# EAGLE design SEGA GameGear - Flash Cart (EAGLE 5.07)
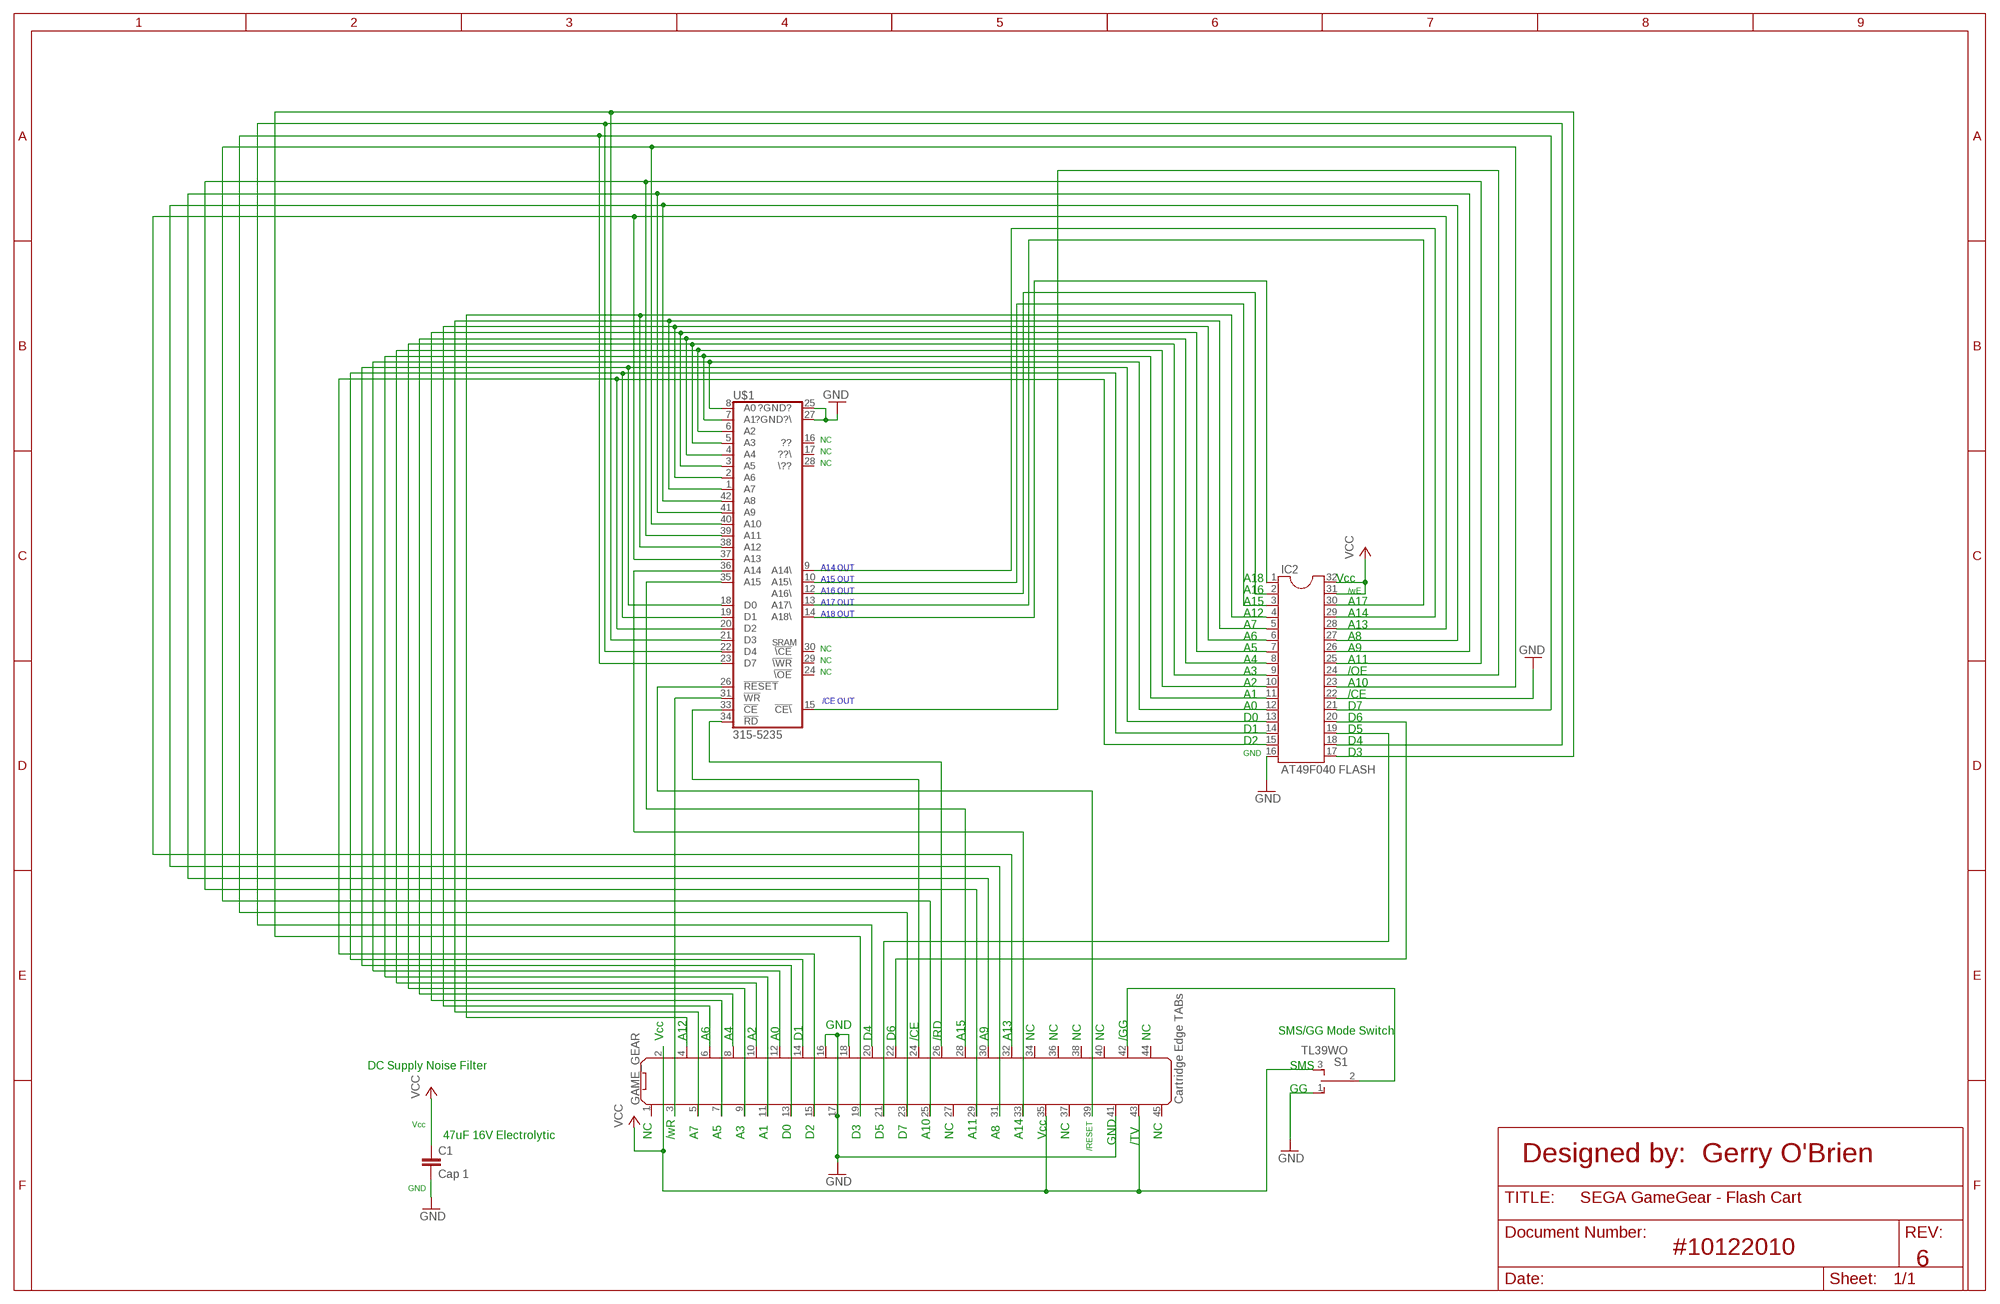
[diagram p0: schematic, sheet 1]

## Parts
C1  Cap 1  C7.5/3  [C7.5B3]
GAME_GEAR  Cartridge Edge TABs  SIP24  [ZIP45]
IC2  AT49F040 FLASH  DIL32  [DIL32]
S1  TL39WO  [TL3XWO]
U$1  315-5235  [DIL42-6.07]

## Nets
GND: C1.2 GAME_GEAR.16 GAME_GEAR.17 GAME_GEAR.18 GAME_GEAR.41 IC2.16 IC2.22 S1.1(O) U$1.25(?GND?) U$1.27(?GND?\)
N$1: GAME_GEAR.4 IC2.4 U$1.38(A12)
N$2: GAME_GEAR.5 IC2.5 U$1.1(A7)
N$3: GAME_GEAR.25 IC2.23 U$1.40(A10)
N$4: GAME_GEAR.29 IC2.25 U$1.39(A11)
N$5: GAME_GEAR.30 IC2.26 U$1.41(A9)
N$6: GAME_GEAR.6 IC2.6 U$1.2(A6)
N$7: GAME_GEAR.32 IC2.28 U$1.37(A13)
N$8: GAME_GEAR.23 IC2.21 U$1.23(D7)
N$9: GAME_GEAR.20 IC2.18 U$1.22(D4)
N$10: GAME_GEAR.12 IC2.12 U$1.8(A0)
N$11: GAME_GEAR.22 IC2.20
N$12: GAME_GEAR.19 IC2.17 U$1.21(D3)
N$13: IC2.24 U$1.15(!CE\)
N$14: GAME_GEAR.14 IC2.14 U$1.19(D1)
N$15: GAME_GEAR.15 IC2.15 U$1.20(D2)
N$16: GAME_GEAR.13 IC2.13 U$1.18(D0)
N$17: GAME_GEAR.8 IC2.8 U$1.4(A4)
N$18: GAME_GEAR.11 IC2.11 U$1.7(A1)
N$19: GAME_GEAR.10 IC2.10 U$1.6(A2)
N$20: GAME_GEAR.21 IC2.19
N$21: GAME_GEAR.7 IC2.7 U$1.3(A5)
N$22: GAME_GEAR.9 IC2.9 U$1.5(A3)
N$23: GAME_GEAR.39 U$1.26(!RESET)
N$24: IC2.29 U$1.9(A14\)
N$25: GAME_GEAR.31 IC2.27 U$1.42(A8)
N$26: IC2.30 U$1.13(A17\)
N$27: IC2.1 U$1.14(A18\)
N$28: IC2.2 U$1.12(A16\)
N$29: GAME_GEAR.42 S1.2(P)
N$30: IC2.3 U$1.10(A15\)
N$31: GAME_GEAR.3 U$1.31(!WR)
N$32: GAME_GEAR.24 U$1.33(!CE)
N$33: GAME_GEAR.26 U$1.34(!RD)
N$34: GAME_GEAR.28 U$1.35(A15)
N$35: GAME_GEAR.33 U$1.36(A14)
VCC: C1.1 GAME_GEAR.2 GAME_GEAR.35 GAME_GEAR.43 IC2.31 IC2.32 S1.3(S)
Unconnected: GAME_GEAR.1 GAME_GEAR.27 GAME_GEAR.34 GAME_GEAR.36 GAME_GEAR.37 GAME_GEAR.38 GAME_GEAR.40 GAME_GEAR.44 GAME_GEAR.45 U$1.16(??) U$1.17(??\) U$1.24(!\OE) U$1.28(\??) U$1.29(!\WR) U$1.30(!\CE)

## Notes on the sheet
- NC
- NC
- NC
- A14 OUT
- A15 OUT
- A18 | Vcc
- A16 OUT
- A16 | /wE
- A17 OUT
- A15 | A17
- A18 OUT
- A12 | A14
- A7 | A13
- A6 | A8
- NC
- A5 | A9
- NC
- A4 | A11
- NC
- A3 | /OE
- A2 | A10
- /CE OUT | A1 | /CE
- A0 | D7
- D0 | D6
- D1 | D5
- D2 | D4
- GND | D3
- GND
- SMS/GG Mode Switch
- Vcc | A12 | A6 | A4 | A2 | A0 | D1 | D4 | D6 | /CE | /RD | A15 | A9 | A13 | NC | NC | NC | NC | /GG | NC
- DC Supply Noise Filter | SMS
- GG
- Vcc
- 47uF 16V Electrolytic | NC | /wR | A7 | A5 | A3 | A1 | D0 | D2 | D3 | D5 | D7 | A10 | NC | A11 | A8 | A14 | Vcc | NC | NC
- GND | /TV
- /RESET
- Designed by:  Gerry O'Brien
- GND
- #10122010
- 6

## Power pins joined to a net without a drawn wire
GND: U$1.11(GND)
VCC: U$1.32(VCC)

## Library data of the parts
C1 = capacitor-wima:C: CAPACITOR
GAME_GEAR = 2010.09.20:SIP24: Single In Line Modified to resemble Game Gear card edge connector. Pins would ideally be 0.15" long and not have holes in them. Pads will be replaced with polygons once dimensions have been verified. Drawn by Darren Lue Choy &micro; 2010.09.21
IC2 = ic-package:DIL32: Dual In Line
S1 = switch:TL39WO: TINY SWITCH ON OFF ON Source: http://www2.produktinfo.conrad.com/datenblaetter/700000-724999/705152-da-01-de-Subminiaturschalter_TL_36WO.pdf
U$1 = 2010.09.20:315-5235: Sega 315-5235 Paging Chip Currently, it is believed that the 315-5235 paging chip can handle up to 32 &times; 16KByte memory pages, making it suitable for use with 1, 2, and 4 Megabit games. Additionally, this chip is believed to contain the logic necessary for handling battery-backup RAM. The fact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

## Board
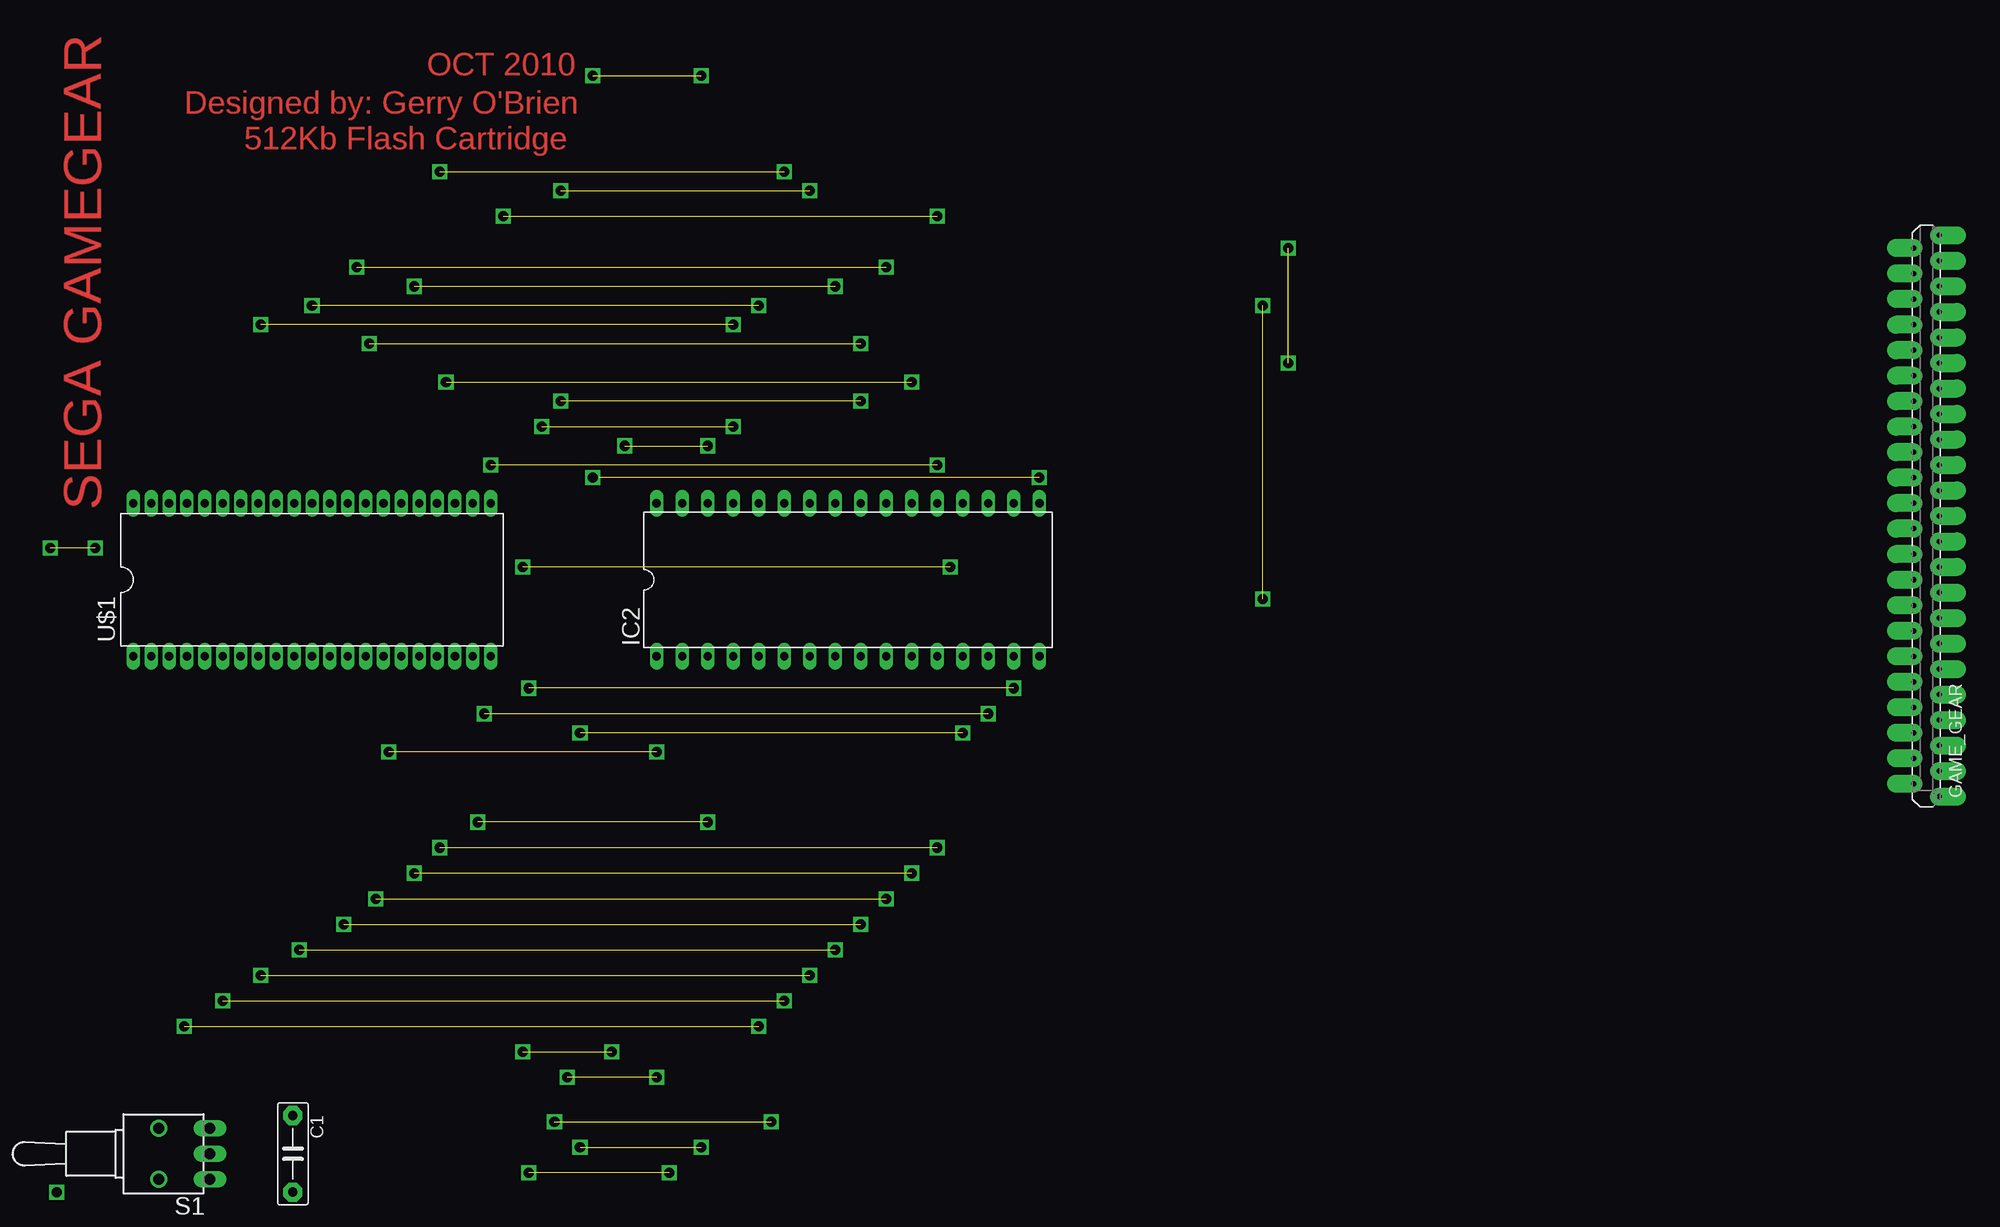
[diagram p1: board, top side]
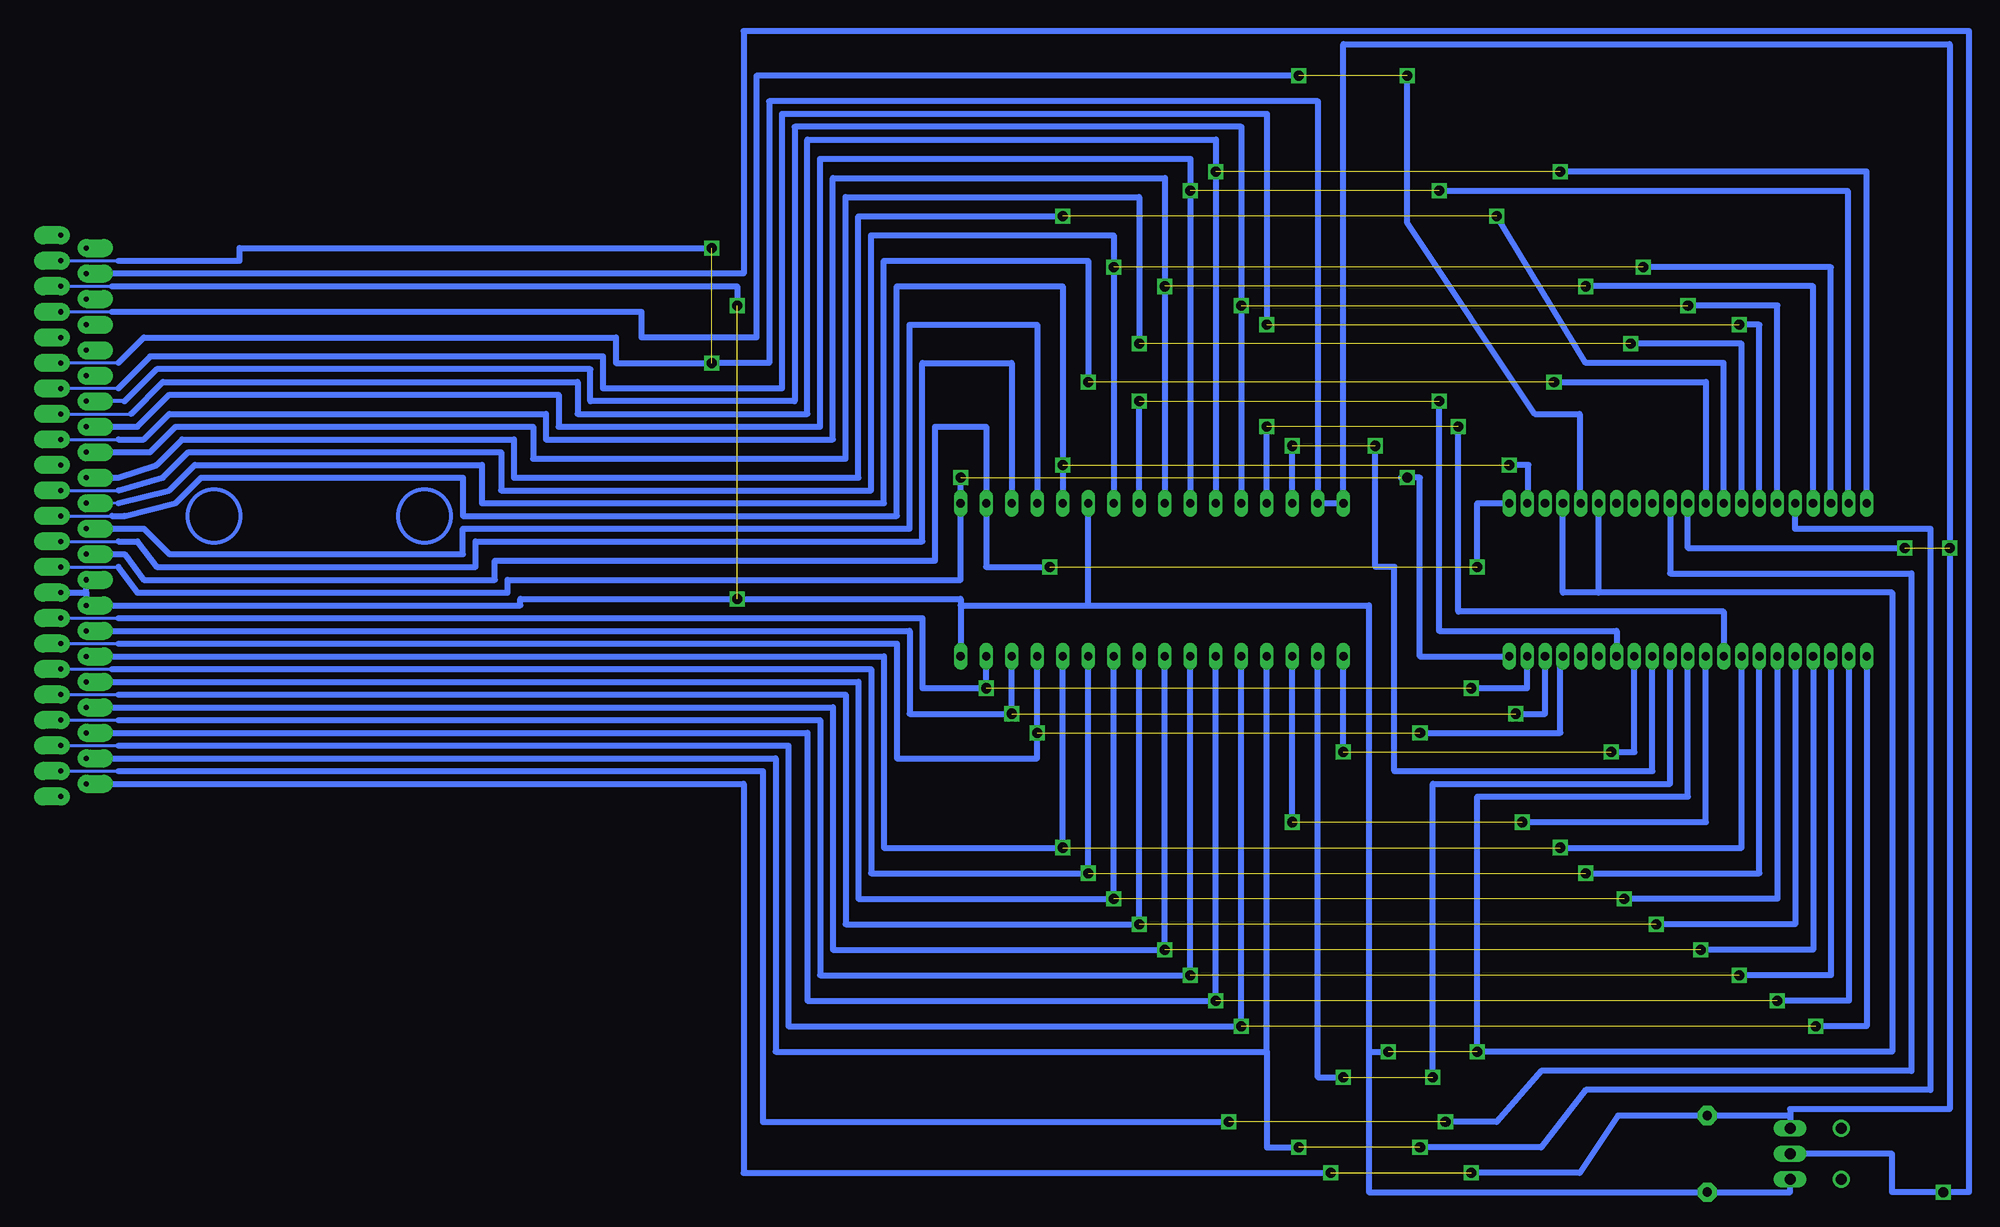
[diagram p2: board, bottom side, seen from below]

No outline drawn. Coordinates in mm, seen from the top.
Copper layers (1*16): Top 0.035mm / dielectric 1.5mm / Bottom 0.035mm
Design rules "default": minimum track width 10mil, minimum drill 24mil, track to track 8mil, track to pad 8mil, pad to pad 8mil, via to via 8mil, smd to smd 8mil, copper to edge 40mil, drill to drill 8mil, minimum pad ring 10mil, minimum via ring 8mil, stop-mask expansion 4mil, vias tented up to drill 0mil, thermal gap 10mil

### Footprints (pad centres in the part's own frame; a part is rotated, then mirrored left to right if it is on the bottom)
C7.5B3 = drill 0.914 pad 1.905 octagon: 1 -3.81,0; 2 3.81,0
ZIP45 = drill 0.5 pad 1.778 offset: 1 -27.94,-1.27; 2 -26.67,1.27; 3 -25.4,-1.27; 4 -24.13,1.27; 5 -22.86,-1.27; 6 -21.59,1.27; 7 -20.32,-1.27; 8 -19.05,1.27; 9 -17.78,-1.27; 10 -16.51,1.27; 11 -15.24,-1.27; 12 -13.97,1.27; 13 -12.7,-1.27; 14 -11.43,1.27; 15 -10.16,-1.27; 16 -8.89,1.27; 17 -7.62,-1.27; 18 -6.35,1.27; 19 -5.08,-1.27; 20 -3.81,1.27; 21 -2.54,-1.27; 22 -1.27,1.27; 23 0,-1.27; 24 1.27,1.27; 25 2.54,-1.27; 26 3.81,1.27; 27 5.08,-1.27; 28 6.35,1.27; 29 7.62,-1.27; 30 8.89,1.27; 31 10.16,-1.27; 32 11.43,1.27; 33 12.7,-1.27; 34 13.97,1.27; 35 15.24,-1.27; 36 16.51,1.27; 37 17.78,-1.27; 38 19.05,1.27; 39 20.32,-1.27; 40 21.59,1.27; 41 22.86,-1.27; 42 24.13,1.27; 43 25.4,-1.27; 44 26.67,1.27; 45 27.94,-1.27
DIL32 = drill 0.813 long: 1 -19.05,-7.62; 2 -16.51,-7.62; 3 -13.97,-7.62; 4 -11.43,-7.62; 5 -8.89,-7.62; 6 -6.35,-7.62; 7 -3.81,-7.62; 8 -1.27,-7.62; 9 1.27,-7.62; 10 3.81,-7.62; 11 6.35,-7.62; 12 8.89,-7.62; 13 11.43,-7.62; 14 13.97,-7.62; 15 16.51,-7.62; 16 19.05,-7.62; 17 19.05,7.62; 18 16.51,7.62; 19 13.97,7.62; 20 11.43,7.62; 21 8.89,7.62; 22 6.35,7.62; 23 3.81,7.62; 24 1.27,7.62; 25 -1.27,7.62; 26 -3.81,7.62; 27 -6.35,7.62; 28 -8.89,7.62; 29 -11.43,7.62; 30 -13.97,7.62; 31 -16.51,7.62; 32 -19.05,7.62
TL3XWO = drill 1.1 pad 1.422 long: 1 -2.54,-5.08; 2 0,-5.08; 3 2.54,-5.08 | drill 1.1 pad 1.676 round: M1 -2.54,0; M2 2.54,0
DIL42-6.07 = drill 0.813 long: 1 -17.78,-7.62; 2 -16.002,-7.62; 3 -14.224,-7.62; 4 -12.446,-7.62; 5 -10.668,-7.62; 6 -8.89,-7.62; 7 -7.112,-7.62; 8 -5.334,-7.62; 9 -3.556,-7.62; 10 -1.778,-7.62; 11 0,-7.62; 12 1.778,-7.62; 13 3.556,-7.62; 14 5.334,-7.62; 15 7.112,-7.62; 16 8.89,-7.62; 17 10.668,-7.62; 18 12.446,-7.62; 19 14.224,-7.62; 20 16.002,-7.62; 21 17.78,-7.62; 22 17.78,7.62; 23 16.002,7.62; 24 14.224,7.62; 25 12.446,7.62; 26 10.668,7.62; 27 8.89,7.62; 28 7.112,7.62; 29 5.334,7.62; 30 3.556,7.62; 31 1.778,7.62; 32 0,7.62; 33 -1.778,7.62; 34 -3.556,7.62; 35 -5.334,7.62; 36 -7.112,7.62; 37 -8.89,7.62; 38 -10.668,7.62; 39 -12.446,7.62; 40 -14.224,7.62; 41 -16.002,7.62; 42 -17.78,7.62

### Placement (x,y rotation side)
C1  32.38,9.53 270 top
GAME_GEAR  194.94,73.03 90 top
IC2  87.63,66.67 0 top
S1  19.05,9.53 90 top
U$1  34.29,66.67 0 top

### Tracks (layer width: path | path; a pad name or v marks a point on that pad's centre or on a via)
GND  (via drill 1)  (2 unrouted)
  Bottom 0.305: GAME_GEAR.41 191.13,95.89
  Bottom 0.61: 93.98,64.14 IC2.22 | 93.98,64.14 66.04,64.14 66.04,19.68 | 66.04,19.68 v64.14,19.68 | 66.04,19.68 66.04,5.71 C1.2 24.13,5.71 S1.1 | 106.68,64.14 93.98,64.14 | 106.68,64.14 IC2.16 | 193.68,65.41 GAME_GEAR.16 150.5,64.14 150.5,64.77 v128.91,64.77 106.68,64.77 106.68,64.14 | 193.68,65.41 GAME_GEAR.18 | GAME_GEAR.17 193.68,65.41 | 191.13,95.89 128.91,95.89 v128.91,93.98 | U$1.11 34.29,45.09 55.24,45.09 v55.24,19.68 13.97,19.68 13.97,65.41 43.18,65.41 | U$1.25 46.74,65.41 43.18,65.41 | 43.18,65.41 U$1.27
N$1  (via drill 1)  (1 unrouted)
  Bottom 0.61: GAME_GEAR.4 125.09,48.9 125.09,19.68 76.2,19.68 | 76.2,19.68 76.2,10.16 v73.03,10.16 | 76.2,19.68 IC2.4 | U$1.38 23.62,71.75 10.16,71.75 10.16,15.88 44.45,15.88 48.9,10.16 v60.96,10.16
N$2  (via drill 1)  (1 unrouted)
  Bottom 0.305: GAME_GEAR.5 190.5,50.16
  Bottom 0.61: 190.5,50.16 123.83,50.16 123.83,22.23 v78.74,22.23 IC2.5 | U$1.1 16.51,22.23 v21.59,22.23
N$3  (via drill 1)  (1 unrouted)
  Bottom 0.305: GAME_GEAR.25 190.5,75.56
  Bottom 0.61: 190.5,75.56 186.06,76.83 183.51,79.38 152.4,79.38 152.4,75.56 115.57,75.56 115.57,100.97 91.44,100.97 v91.44,97.79 IC2.23 | U$1.40 20.07,97.79 v38.73,97.79
N$4  (via drill 1)  (1 unrouted)
  Bottom 0.305: GAME_GEAR.29 190.5,80.64
  Bottom 0.406: U$1.39 21.59,74.3
  Bottom 0.61: 190.5,80.64 187.96,80.64 185.42,83.19 147.96,83.19 147.96,80.64 119.38,80.64 119.38,106.68 86.36,106.68 v86.36,95.89 IC2.25 | U$1.39 21.84,95.89 v44.45,95.89
N$5  (via drill 1)  (1 unrouted)
  Bottom 0.406: 18.41,74.42 U$1.41
  Bottom 0.61: IC2.26 v83.82,105.41 83.82,108.58 120.65,108.58 120.65,81.92 146.69,81.92 146.69,85.09 185.42,85.09 188.59,81.92 GAME_GEAR.30 | v59.05,105.41 18.41,105.41 18.41,74.42
N$6  (via drill 1)  (1 unrouted)
  Bottom 0.61: GAME_GEAR.6 121.92,51.44 121.92,24.77 v81.28,24.77 IC2.6 | U$1.2 18.29,24.77 v25.4,24.77
N$7  (via drill 1)  (1 unrouted)
  Bottom 0.406: 189.87,84.45 GAME_GEAR.32
  Bottom 0.61: 189.87,84.45 186.69,87.63 143.51,87.63 143.51,84.45 123.19,84.45 123.19,111.76 78.74,111.76 v78.74,93.98 IC2.28 | U$1.37 25.4,93.98 v34.29,93.98
N$8  (via drill 1)  (1 unrouted)
  Bottom 0.305: GAME_GEAR.23 191.13,73.03
  Bottom 0.406: U$1.23 50.16,74.3
  Bottom 0.61: 191.13,73.03 189.87,73.03 184.78,74.3 182.25,76.83 156.21,76.83 156.21,73.03 113.03,73.03 113.03,95.89 96.52,95.89 v96.52,78.11 IC2.21 | 50.16,74.3 50.16,78.11 v52.07,78.11
N$9  (via drill 1)  (1 unrouted)
  Bottom 0.61: GAME_GEAR.20 189.87,69.22 187.96,66.67 153.03,66.67 153.03,68.58 109.22,68.58 109.22,81.92 104.14,81.92 IC2.18 104.14,67.94 v97.79,67.94 | U$1.22 55.24,74.3 v55.24,67.94
N$10  (via drill 1)  (1 unrouted)
  Bottom 0.61: IC2.12 v96.52,40.01 114.3,40.01 114.3,59.05 GAME_GEAR.12 | U$1.8 28.96,40.01 v46.99,40.01
N$11
  Bottom 0.61: GAME_GEAR.22 187.96,71.75 185.42,69.22 156.21,69.22 156.21,71.75 111.76,71.75 111.76,92.08 99.06,92.08 IC2.20
N$12  (via drill 1)  (1 unrouted)
  Bottom 0.305: GAME_GEAR.19 190.5,67.94
  Bottom 0.61: 190.5,67.94 188.59,65.41 151.76,65.41 151.76,66.67 106.68,66.67 IC2.17 v106.68,76.83 | U$1.21 60.96,59.05 60.96,76.83 v62.23,76.83 62.87,76.83
N$13  (via drill 1)  (1 unrouted)
  Bottom 0.61: IC2.24 v88.9,84.45 | U$1.15 41.4,61.59 59.05,61.59 v59.05,84.45
N$14  (via drill 1)  (1 unrouted)
  Bottom 0.61: IC2.14 v101.6,53.34 111.76,53.34 111.76,61.59 GAME_GEAR.14 | U$1.19 48.51,53.34 v51.44,53.34
N$15  (via drill 1)  (1 unrouted)
  Bottom 0.305: GAME_GEAR.15 190.5,62.87
  Bottom 0.406: v104.14,55.88 104.14,57.15
  Bottom 0.61: 190.5,62.87 110.49,62.87 110.49,55.88 v104.14,55.88 IC2.15 | U$1.20 50.29,55.88 v55.88,55.88
N$16  (via drill 1)  (1 unrouted)
  Bottom 0.305: GAME_GEAR.13 190.5,60.33
  Bottom 0.406: 46.99,59.05 U$1.18
  Bottom 0.61: 190.5,60.33 113.03,60.33 113.03,48.9 99.06,48.9 v99.06,51.44 IC2.13 | 46.99,59.05 46.99,51.44 v60.96,51.44
N$17  (via drill 1)  (1 unrouted)
  Bottom 0.61: GAME_GEAR.8 119.38,53.98 119.38,29.84 v86.36,29.84 IC2.8 | U$1.4 21.84,29.84 v33.02,29.84
N$18  (via drill 1)  (1 unrouted)
  Bottom 0.305: GAME_GEAR.11 191.13,57.78
  Bottom 0.61: 191.13,57.78 115.57,57.78 115.57,37.47 v93.98,37.47 IC2.11 | U$1.7 27.18,37.47 v44.45,37.47
N$19  (via drill 1)  (1 unrouted)
  Bottom 0.61: IC2.10 v91.44,34.92 116.84,34.92 116.84,56.52 GAME_GEAR.10 | U$1.6 25.4,34.92 v40.64,34.92
N$20
  Bottom 0.305: GAME_GEAR.21 190.5,70.48
  Bottom 0.61: 190.5,70.48 188.59,70.48 186.69,67.94 154.94,67.94 154.94,70.48 110.49,70.48 110.49,88.27 101.6,88.27 IC2.19
N$21  (via drill 1)  (1 unrouted)
  Bottom 0.305: GAME_GEAR.7 190.5,52.7
  Bottom 0.61: 190.5,52.7 120.65,52.7 120.65,27.3 v83.82,27.3 IC2.7 | U$1.3 20.07,27.3 v29.21,27.3
N$22  (via drill 1)  (1 unrouted)
  Bottom 0.305: GAME_GEAR.9 190.5,55.24
  Bottom 0.61: IC2.9 v88.9,32.38 118.11,32.38 118.11,55.24 190.5,55.24 | U$1.5 23.62,32.38 v37.47,32.38
N$23  (via drill 1)  (1 unrouted)
  Bottom 0.305: 191.13,93.34 GAME_GEAR.39
  Bottom 0.406: U$1.26 44.96,74.17 45.09,74.3
  Bottom 0.61: 191.13,93.34 138.43,93.34 138.43,90.81 127,90.81 127,116.84 v73.03,116.84 | 45.09,74.3 45.09,83.19 49.53,83.19 62.23,102.23 v62.23,116.84
N$24  (via drill 1)  (1 unrouted)
  Bottom 0.61: IC2.29 v76.2,81.92 | U$1.9 30.73,63.5 57.15,63.5 v57.15,81.92
N$25  (via drill 1)  (1 unrouted)
  Bottom 0.305: GAME_GEAR.31 189.23,83.19
  Bottom 0.61: 189.23,83.19 186.06,86.36 144.78,86.36 144.78,83.19 121.92,83.19 121.92,110.49 81.28,110.49 v81.28,107.31 IC2.27 | U$1.42 16.51,107.31 v46.99,107.31
N$26  (via drill 1)  (1 unrouted)
  Bottom 0.61: IC2.30 v73.66,80.01 | U$1.13 37.85,47.62 63.5,47.62 63.5,67.94 65.41,67.94 v65.41,80.01
N$27  (via drill 1)  (1 unrouted)
  Bottom 0.61: v68.58,49.53 IC2.1 | U$1.14 39.62,49.53 v41.91,49.53
N$28  (via drill 1)  (1 unrouted)
  Bottom 0.61: IC2.2 71.12,17.14 v68.58,17.14 | U$1.12 36.07,46.35 59.69,46.35 v59.69,17.14
N$29  (via drill 1)
  Bottom 0.61: S1.2 13.97,9.53 13.97,5.71 v8.89,5.71 6.35,5.71 6.35,121.28 128.27,121.28 128.27,97.16 GAME_GEAR.42
N$30  (via drill 1)  (1 unrouted)
  Bottom 0.61: v73.66,42.55 IC2.3 | U$1.10 32.51,42.55 v50.8,42.55
N$31  (via drill 1)  (1 unrouted)
  Bottom 0.305: GAME_GEAR.3 190.5,47.62
  Bottom 0.61: 190.5,47.62 126.36,47.62 126.36,12.7 v80.01,12.7 | U$1.31 36.07,67.31 12.06,67.31 12.06,17.78 48.9,17.78 53.34,12.7 v58.42,12.7
N$32  (via drill 1)  (1 unrouted)
  Bottom 0.254: GAME_GEAR.24 190.5,74.3
  Bottom 0.61: 190.5,74.3 185.42,75.56 182.88,78.11 154.31,78.11 154.31,74.3 114.3,74.3 114.3,98.42 93.98,98.42 v93.98,86.36 | U$1.33 32.51,86.36 v47.62,86.36
N$33  (via drill 1)  (1 unrouted)
  Bottom 0.61: GAME_GEAR.26 190.5,76.83 186.69,78.11 184.15,80.64 151.13,80.64 151.13,76.83 116.84,76.83 116.84,102.87 v96.52,102.87 | v53.34,102.87 44.45,88.27 30.73,88.27 U$1.34
N$34  (via drill 1)  (1 unrouted)
  Bottom 0.61: GAME_GEAR.28 187.32,79.38 184.78,81.92 149.22,81.92 149.22,78.74 118.11,78.74 118.11,104.78 88.9,104.78 v88.9,90.17 | U$1.35 28.96,90.17 v40.01,90.17
N$35  (via drill 1)  (1 unrouted)
  Bottom 0.305: 190.5,85.72 GAME_GEAR.33
  Bottom 0.61: 190.5,85.72 187.32,88.9 142.24,88.9 142.24,85.72 124.46,85.72 124.46,113.03 76.2,113.03 v76.2,92.08 | U$1.36 27.18,92.08 v29.21,92.08
VCC  (via drill 1)  (3 unrouted)
  Bottom 0.305: 190.5,88.27 GAME_GEAR.35 | GAME_GEAR.43 190.5,98.42
  Bottom 0.61: 190.5,88.27 187.96,90.81 140.97,90.81 140.97,88.27 v131.44,88.27 125.73,88.27 125.73,114.3 71.12,114.3 IC2.31 IC2.32 68.58,120.02 8.26,120.02 v8.26,69.85 8.26,13.97 24.13,13.97 24.13,13.34 | 190.5,98.42 178.44,98.42 178.44,99.69 v131.44,99.69 | U$1.32 34.29,69.85 v12.7,69.85 | GAME_GEAR.2 128.27,46.35 128.27,7.62 v69.85,7.62 | v55.88,7.62 45.09,7.62 41.27,13.34 C1.1 24.13,13.34 | 24.13,13.34 S1.3
(copper drawn outside any net)
  shapes: Bottom circle x2

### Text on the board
Top: OCT 2010 | Designed by: Gerry O'Brien | 512Kb Flash Cartridge | SEGA GAMEGEAR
